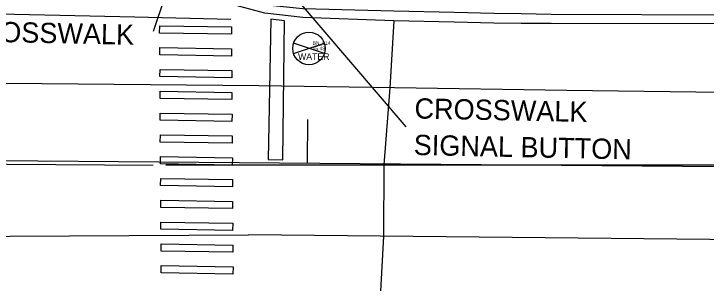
# Model space of a CAD drawing. Extents: x 509744 to 512285, y 1314862 to 1316822.
# Drawn here: x 511226.8 to 511322.6, y 1315603.7 to 1315640.8 of the extents above; entities that cross this region are included whole.
import ezdxf

# ---------------------------------------------------------------- set-up
doc = ezdxf.new("R2010")
doc.units = 0
for name, color, linetype in [('BaselineSurvey', 7, 'Continuous'), ('CGep_ep', 7, 'Continuous'), ('LaneLine_ep', 7, 'Continuous'), ('PavtAsphalt_ep', 7, 'Continuous'), ('PavtAsphaltCrown_ep', 7, 'Continuous'), ('PavtBreak_ep', 7, 'Continuous'), ('PMRK_ep', 7, 'Continuous'), ('TextElevLabel', 7, 'Continuous'), ('TextPtLabel', 7, 'Continuous'), ('TextTopoLabel_ep', 7, 'Continuous'), ('ValveCvrWater_ep', 7, 'Continuous')]:
    doc.layers.add(name, color=color, linetype=linetype)

msp = doc.modelspace()

# ---------------------------------------------------------------- linework, layer by layer
at = {"layer": 'BaselineSurvey'}
for p, q in [((511267.427, 1315620.255), (511267.478, 1315626.254)), ((511105.396, 1315621.625), (512116.976, 1315613.07))]:
    msp.add_line(p, q, dxfattribs=at)
at = {"layer": 'CGep_ep'}
msp.add_lwpolyline([(511326.139, 1315640.674), (511301.139, 1315640.769), (511296.962, 1315640.864), (511293.19, 1315640.886), (511287.696, 1315641.033), (511279.369, 1315641.217), (511266.76, 1315641.547), (511261.787, 1315642.062), (511256.957, 1315643.335), (511253.563, 1315644.851), (511249.683, 1315647.346), (511245.915, 1315650.707), (511243.336, 1315653.898), (511240.678, 1315658.133), (511238.865, 1315662.874), (511238.491, 1315663.998), (511237.632, 1315668.623), (511237.144, 1315673.6), (511236.773, 1315678.587), (511235.175, 1315698.207), (511232.297, 1315734.79)], dxfattribs=at)
at = {"layer": 'LaneLine_ep'}
for points in [[(511453.274, 1315628.504), (511428.275, 1315628.794), (511403.277, 1315629.083), (511378.279, 1315629.373), (511353.28, 1315629.663), (511328.282, 1315629.953), (511303.284, 1315630.243), (511279.454, 1315630.634), (511260.694, 1315630.916)], [(512038.761, 1315604.266), (511985.055, 1315604.266), (511938.06, 1315604.587), (511812.246, 1315605.744), (511715.361, 1315606.172), (511673.635, 1315606.62), (511627.056, 1315607.12), (511592.806, 1315607.487), (511560.073, 1315607.838), (511514.08, 1315608.332), (511464.378, 1315608.249), (511259.262, 1315610.317)]]:
    msp.add_lwpolyline(points, dxfattribs=at)
at = {"layer": 'PavtAsphalt_ep'}
msp.add_lwpolyline([(511326.127, 1315639.449), (511301.127, 1315639.491), (511296.949, 1315639.532), (511293.178, 1315639.569), (511287.683, 1315639.715), (511279.356, 1315639.9), (511266.748, 1315640.347), (511261.49, 1315640.96), (511256.66, 1315642.233), (511252.929, 1315643.903), (511249.049, 1315646.398), (511245.15, 1315649.562), (511242.344, 1315653.305), (511239.598, 1315657.488), (511237.784, 1315662.228), (511237.411, 1315663.352), (511236.45, 1315668.535), (511235.962, 1315673.512), (511235.591, 1315678.499), (511233.994, 1315698.119), (511233.382, 1315708.654), (511231.295, 1315708.723), (511229.081, 1315734.538)], dxfattribs=at)
at = {"layer": 'PavtAsphaltCrown_ep'}
msp.add_lwpolyline([(511247.797, 1315620.002), (511272.796, 1315620.002), (511289.606, 1315620.002), (511314.606, 1315620.002), (511331.416, 1315620.002), (511356.408, 1315619.401), (511374.351, 1315618.971), (511399.343, 1315618.37), (511420.096, 1315617.872), (511445.089, 1315618.427)], dxfattribs=at)
at = {"layer": 'PavtBreak_ep'}
for points in [[(511143.568, 1315642.61), (511168.558, 1315642.06), (511218.54, 1315640.962), (511243.531, 1315640.413), (511256.789, 1315640.122)], [(511279.356, 1315639.9), (511278.793, 1315630.644), (511277.974, 1315620.002), (511277.902, 1315610.129), (511277.385, 1315600.043)], [(511260.694, 1315630.916), (511235.698, 1315631.136), (511210.701, 1315631.356), (511185.704, 1315631.577), (511135.711, 1315632.018), (511124.373, 1315632.118)], [(511125.891, 1315620.769), (511175.885, 1315620.428), (511225.879, 1315620.087), (511246.069, 1315619.949)], [(511126.233, 1315609.679), (511176.232, 1315609.919), (511201.232, 1315610.038), (511226.231, 1315610.158), (511259.262, 1315610.317)]]:
    msp.add_lwpolyline(points, dxfattribs=at)
at = {"layer": 'PMRK_ep'}
msp.add_lwpolyline([(511262.348, 1315640.119), (511261.983, 1315620.754), (511263.977, 1315620.679), (511264.224, 1315639.861), (511262.348, 1315640.119)], dxfattribs=at)
for points in [[(511246.975, 1315639.197), (511256.901, 1315639.033), (511256.886, 1315638.034), (511246.96, 1315638.197)], [(511246.994, 1315636.186), (511256.92, 1315636.023), (511256.905, 1315635.023), (511246.979, 1315635.187)], [(511247.013, 1315633.176), (511256.939, 1315633.012), (511256.923, 1315632.013), (511246.997, 1315632.176)], [(511247.032, 1315630.165), (511256.958, 1315630.002), (511256.942, 1315629.002), (511247.016, 1315629.166)], [(511247.051, 1315627.155), (511256.977, 1315626.991), (511256.961, 1315625.992), (511247.035, 1315626.155)], [(511247.07, 1315624.144), (511256.996, 1315623.981), (511256.979, 1315622.981), (511247.053, 1315623.145)], [(511247.088, 1315621.134), (511257.014, 1315620.97), (511256.998, 1315619.971), (511247.072, 1315620.134)], [(511247.107, 1315618.123), (511257.033, 1315617.96), (511257.017, 1315616.96), (511247.091, 1315617.124)], [(511247.126, 1315615.113), (511257.052, 1315614.95), (511257.035, 1315613.95), (511247.109, 1315614.113)], [(511247.145, 1315612.102), (511257.071, 1315611.939), (511257.054, 1315610.939), (511247.128, 1315611.103)], [(511247.164, 1315609.092), (511257.09, 1315608.929), (511257.073, 1315607.929), (511247.147, 1315608.092)], [(511247.182, 1315606.081), (511257.108, 1315605.918), (511257.091, 1315604.919), (511247.165, 1315605.082)]]:
    msp.add_lwpolyline(points, close=True, dxfattribs=at)
at = {"layer": 'TextTopoLabel_ep'}
for p, q in [((511281.07, 1315625.227), (511254.405, 1315656.404)), ((511246.117, 1315638.442), (511251.359, 1315654.053))]:
    msp.add_line(p, q, dxfattribs=at)
at = {"layer": 'ValveCvrWater_ep'}
for p, q in [((511265.48, 1315635.353), (511269.749, 1315636.776)), ((511269.749, 1315635.353), (511265.48, 1315636.776))]:
    msp.add_line(p, q, dxfattribs=at)
msp.add_circle((511267.614, 1315636.064), 2.25, dxfattribs=at)

# ---------------------------------------------------------------- texts
at = {"layer": 'TextElevLabel'}
msp.add_text('15.48', height=0.5, dxfattribs=at).set_placement((511268.114, 1315635.814))
at = {"layer": 'TextPtLabel'}
msp.add_text('BN_614', height=0.5, dxfattribs=at).set_placement((511268.114, 1315636.564))
at = {"layer": 'TextTopoLabel_ep'}
for s, p in [('USE CROSSWALK', (511210.74, 1315637.241)), ('CROSSWALK', (511282.189, 1315626.405)), ('SIGNAL BUTTON', (511282.084, 1315621.366))]:
    msp.add_text(s, height=2.8, rotation=358.80879, dxfattribs=at).set_placement(p)
at = {"layer": 'ValveCvrWater_ep'}
msp.add_text('WATER', height=0.9, dxfattribs=at).set_placement((511266.106, 1315634.489))

doc.saveas('drawing.dxf')
